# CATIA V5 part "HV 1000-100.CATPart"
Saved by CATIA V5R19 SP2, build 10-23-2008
Part number: HV 1000-100
Bounding box of the stored display mesh (mm): x -24.865 to 24.865, y -24.997 to 24.997, z 0 to 257
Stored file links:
  C:\Users\Bora\Desktop\3D KATI MODEL- CATIA PART\HV serisi\HV 1000\HV 1000-100.CATPart
  C:\Program Files\Dassault Systemes\B19\intel_a\reffiles\standard\MetricThickPitch.txt
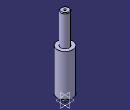
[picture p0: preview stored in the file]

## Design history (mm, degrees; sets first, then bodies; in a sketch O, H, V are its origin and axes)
Body1 (main body)
  Sketch1 on yz-plane, origin (0, 0, 0), H (0, 1, 0), V (0, 0, 1)
    point P1 (14, 255)
    point P3 (14, 255)
    point P8 (8, 17)
    point P10 (8, 1)
    point P11 (8, 17)
    point P12 (8, 1)
    arc A1 centre (12, 255) radius 2 from (14, 255) to (12, 257) ccw
    line L1 (14, 255) -> (14, 156)
    arc A2 centre (8, 18) radius 1 from (8, 19) to (8, 17) ccw
    line L2 (7, 0) -> (8, 1)
    line L3 (8, 17) -> (8, 1)
    line L4 (0, 0) -> (7, 0)
    line L5 (8, 19) -> (25, 19)
    line L6 (14, 156) -> (25, 156)
    line L7 (12, 257) -> (0, 257)
    point P13 (0, 257)
    line L8 (25, 156) -> (25, 19)
    horizontal: L4 H, L6 H
    tangency: L5 A2, L7 A1
    coincidence: P13 V, P1 P3, P8 P11, P10 P12
    vertical: L8 V
  Shaft1: profile Sketch1, axis Sketch1.V, angle 360
  Sketch2 on face of Shaft1 from Sketch1.L4, origin (0, 0, 0), H (1, 0, 0), V (0, -1, 0)
    point P1 (0, 0)
  Hole1: placed by Sketch2, at (0, 0, 0) direction (0, 0, 1), diameter 13.835, depth 19, threaded "M16", thread diameter 16, thread depth 19, pitch 2
  Sketch3 on face of Shaft1 from Sketch1.L7, origin (0, 0, 257), H (1, 0, 0), V (0, 1, 0)
    point P1 (0, 0)
  Hole2: placed by Sketch3, at (0, 0, 257) direction (0, 0, -1), diameter 6.647, depth 15, threaded "M8", thread diameter 8, thread depth 15, pitch 1.25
